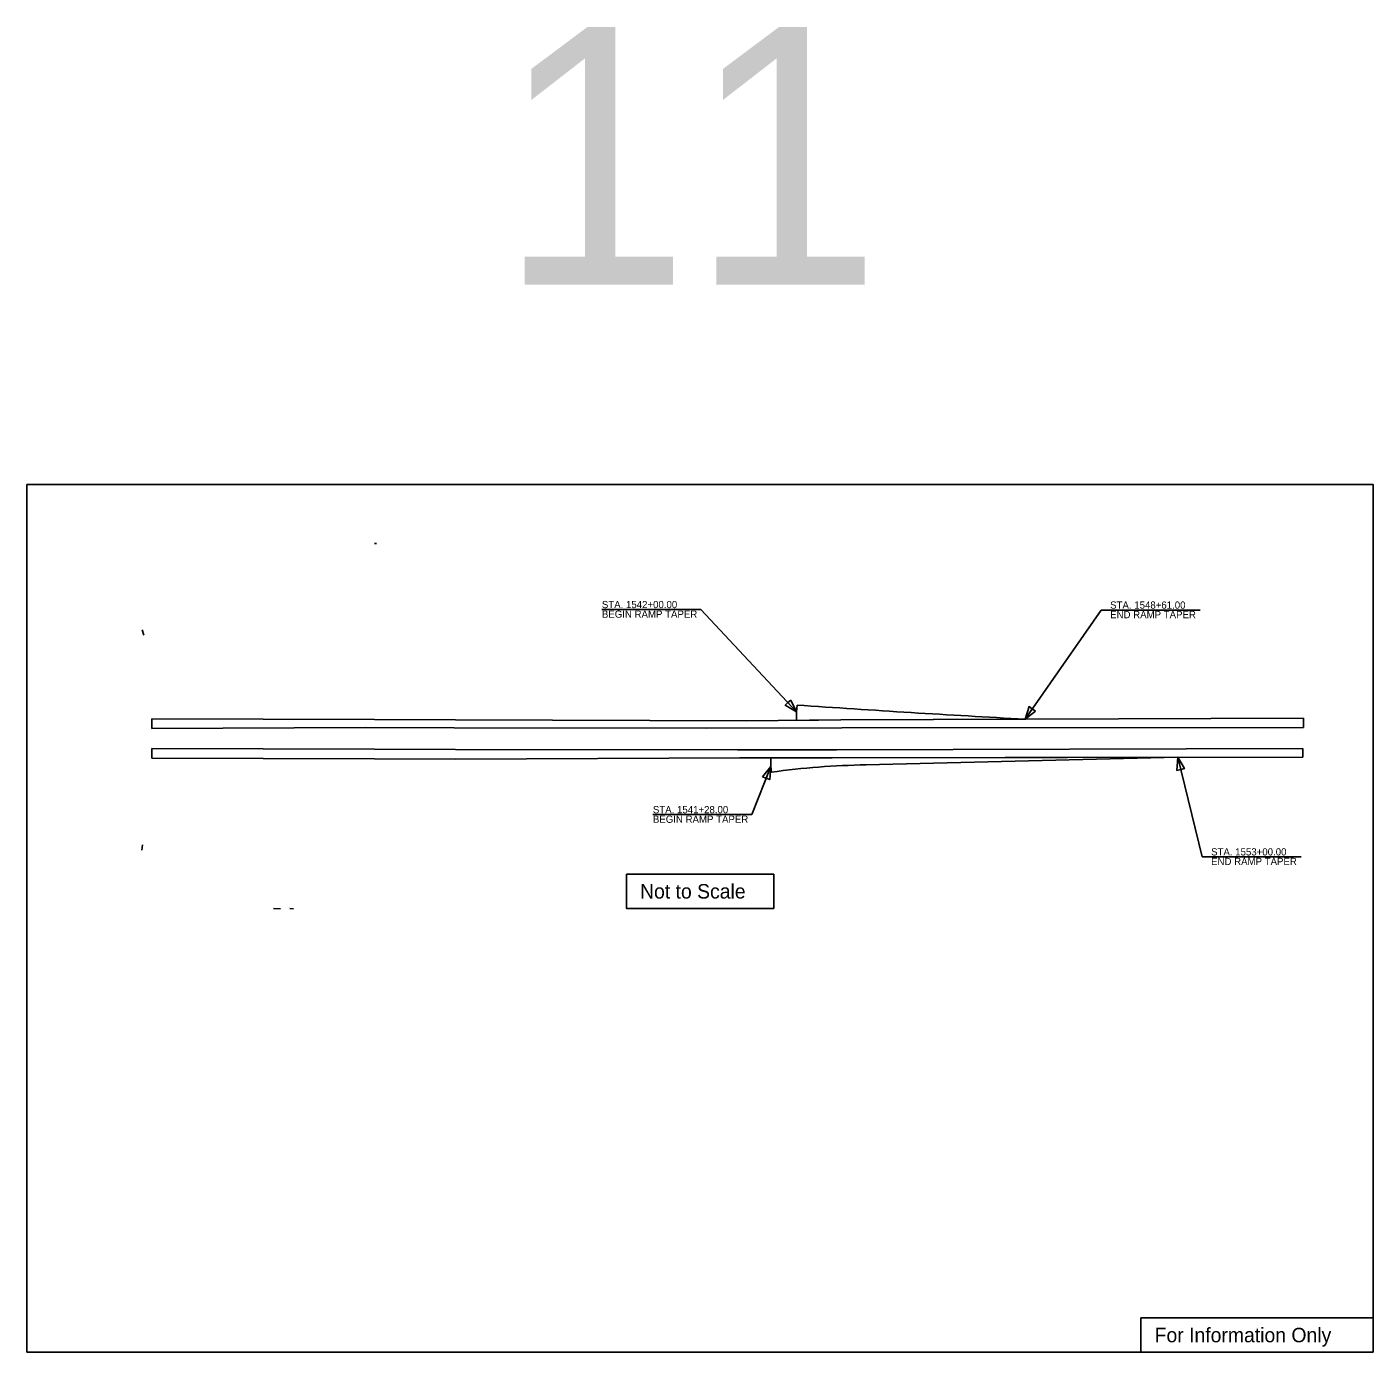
# Model space of a CAD drawing. Extents: x 10133 to 81668, y 7924 to 12255.
# Drawn here: x 46133 to 49268, y 7924 to 11009 of the extents above; entities that cross this region are included whole.
import ezdxf

# ---------------------------------------------------------------- set-up
doc = ezdxf.new("R2010")
doc.units = 0
for name, color, linetype in [('RasterAttachment', 7, 'Continuous'), ('SheetBorder', 7, 'Continuous'), ('SheetText', 7, 'Continuous'), ('Text', 7, 'Continuous')]:
    doc.layers.add(name, color=color, linetype=linetype)

msp = doc.modelspace()

# ---------------------------------------------------------------- linework, layer by layer
at = {"layer": 'RasterAttachment'}
for p, q in [((46946.4, 9806.4), (46942, 9806.4)), ((46404.7, 9593.4), (46401, 9605.9)), ((47926, 9430.5), (47924.9, 9414.7)), ((47924.9, 9394.8), (47924.9, 9414.7)), ((46423.6, 9376), (46423.6, 9398.2)), ((46423.6, 9398.2), (46942.1, 9396.4)), ((46920.4, 9378), (46423.6, 9376)), ((47127.6, 9377.4), (46920.4, 9378)), ((46942.1, 9396.4), (47131, 9395.8)), ((47714.8, 9376.6), (47127.6, 9377.4)), ((47131, 9395.8), (47809.1, 9393.4)), ((48030.3, 9377.2), (47714.8, 9376.6)), ((47809.1, 9393.4), (48027.8, 9395.9)), ((48027.8, 9395.9), (49105.4, 9400.1)), ((49105.4, 9377.8), (48030.3, 9377.2)), ((49105.4, 9400.1), (49105.4, 9377.8)), ((46423.6, 9307), (46423.6, 9329.3)), ((46423.6, 9329.3), (46942.1, 9327.5)), ((46942.1, 9327.5), (47131, 9326.8)), ((47131, 9326.8), (47787.4, 9326.1)), ((47787.4, 9326.1), (48018.1, 9325.9)), ((48018.1, 9325.9), (49103.8, 9329.1)), ((49103.8, 9329.1), (49103.8, 9309.1)), ((46942.1, 9305.2), (46423.6, 9307)), ((47131, 9304.6), (46942.1, 9305.2)), ((47793, 9307.4), (47131, 9304.6)), ((48008, 9307.5), (47793, 9307.4)), ((47864.6, 9307.4), (47864.6, 9287.4)), ((47864.6, 9287.4), (47866.4, 9274.2)), ((49103.8, 9309.1), (48008, 9307.5)), ((48086.6, 9291.2), (48812.6, 9308.7)), ((46401.4, 9105.2), (46400.2, 9092.2)), ((46723.4, 8956.1), (46706.5, 8956.8)), ((46744.6, 8956.4), (46753.2, 8956.3))]:
    msp.add_line(p, q, dxfattribs=at)
for points in [[(48457, 9397.6), (48027.8, 9395.9), (47924.9, 9394.8), (47924.9, 9414.7), (47926, 9430.5)], [(47866.4, 9274.2), (47864.6, 9287.4), (47864.6, 9307.4), (48008, 9307.5), (48812.6, 9308.7), (48086.6, 9291.2)]]:
    msp.add_lwpolyline(points, dxfattribs=at)
for centre, radius, start, end in [((50197.9, 41809.8), 32459, 265.98651, 266.9256), ((50197.9, 41809.8), 32459, 265.98651, 266.9256), ((48122.7, 7390.1), 1901.5, 91.0861, 97.746), ((48122.7, 7390.1), 1901.5, 91.0861, 97.746)]:
    msp.add_arc(centre, radius, start, end, dxfattribs=at)
at = {"layer": 'SheetBorder'}
msp.add_lwpolyline([(46132.5, 9944), (49267.5, 9944), (49267.5, 7924), (46132.5, 7924)], close=True, dxfattribs=at)
at = {"layer": 'SheetText'}
for points in [[(47528.5, 9036.5), (47871.6, 9036.5), (47871.6, 8957.1), (47528.5, 8957.1)], [(48727, 8003.4), (49267.5, 8003.4), (49267.5, 7924), (48727, 7924)]]:
    msp.add_lwpolyline(points, close=True, dxfattribs=at)
at = {"layer": 'Text'}
for p, q in [((47702.1, 9652.7), (47471.6, 9652.7)), ((47924.9, 9414.7), (47702.1, 9652.7)), ((48457, 9397.6), (48634.1, 9651.5)), ((48865.2, 9651.5), (48634.1, 9651.5)), ((47864.6, 9287.4), (47820.8, 9175.2)), ((48812.6, 9308.7), (48869.2, 9076.9)), ((47820.8, 9175.2), (47590.3, 9175.2)), ((49100.2, 9076.9), (48869.2, 9076.9))]:
    msp.add_line(p, q, dxfattribs=at)
for points in [[(47911.4, 9442.1), (47924.9, 9414.7), (47904.9, 9436)], [(47924.9, 9414.7), (47898.4, 9429.9), (47904.9, 9436)], [(48457, 9397.6), (48466.4, 9426.7), (48473.8, 9421.6)], [(48481.1, 9416.5), (48457, 9397.6), (48473.8, 9421.6)], [(47845.6, 9263.4), (47864.6, 9287.4), (47853.9, 9260.1)], [(47864.6, 9287.4), (47862.3, 9256.9), (47853.9, 9260.1)], [(48810.8, 9278.1), (48812.6, 9308.7), (48819.5, 9280.2)], [(48812.6, 9308.7), (48828.2, 9282.3), (48819.5, 9280.2)]]:
    msp.add_lwpolyline(points, close=True, dxfattribs=at)

# ---------------------------------------------------------------- texts
at = {"layer": 'SheetText'}
for s, height, p in [('11', 600, (47230.4, 10409.2)), ('Not to Scale', 33.75, (47560.4, 8979.9)), ('For Information Only', 33.75, (48758.8, 7946.8))]:
    msp.add_text(s, height=height, dxfattribs=at).set_placement(p)
at = {"layer": 'Text'}
for s, p in [('STA. 1542+00.00', (47471.5, 9656)), ('STA. 1548+61.00', (48655.2, 9654.8)), ('BEGIN RAMP TAPER', (47471.5, 9633.7)), ('END RAMP TAPER', (48655.2, 9632.5)), ('STA. 1541+28.00', (47590.3, 9178.5)), ('BEGIN RAMP TAPER', (47590.3, 9156.2)), ('STA. 1553+00.00', (48890.3, 9080.2)), ('END RAMP TAPER', (48890.3, 9057.9))]:
    msp.add_text(s, height=16.8, dxfattribs=at).set_placement(p)

doc.saveas('drawing.dxf')
